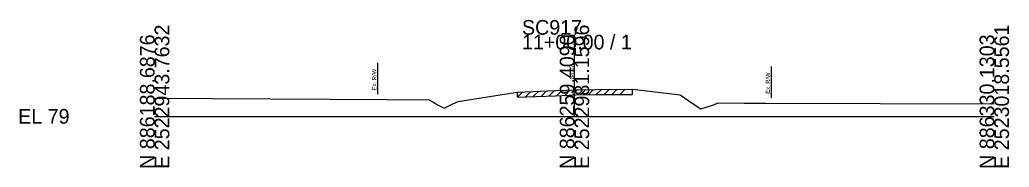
# Model space of a CAD drawing. Extents: x -26 to 218, y -10 to 12021.
# Drawn here: x -25.7 to 162.8, y 9490.3 to 9518.4 of the extents above; entities that cross this region are included whole.
import ezdxf

# ---------------------------------------------------------------- set-up
doc = ezdxf.new("R2010")
doc.units = 0
for name, color, linetype in [('RD_GPK_XS_Cell', 7, 'Continuous'), ('RD_XS_ExGround', 7, 'Continuous'), ('RD_XS_ExPaveRet', 7, 'Continuous'), ('RD_XS_ExRW', 7, 'Continuous'), ('RD_XS_TX_Elev_EX', 7, 'Continuous')]:
    doc.layers.add(name, color=color, linetype=linetype)

msp = doc.modelspace()

# ---------------------------------------------------------------- linework, layer by layer
at = {"layer": 'RD_GPK_XS_Cell'}
for p, q in [((80, 9500), (80, 9515.55)), ((0, 9500), (80, 9500)), ((80, 9500), (160, 9500))]:
    msp.add_line(p, q, dxfattribs=at)
at = {"layer": 'RD_XS_ExGround'}
for p, q in [((57.86, 9502.84), (65.01, 9504)), ((65.01, 9504), (69.14, 9504.63)), ((69.14, 9504.63), (76.39, 9504.93)), ((76.39, 9504.93), (80.26, 9505.08)), ((80.26, 9505.08), (84.01, 9505.13)), ((84.01, 9505.13), (90.97, 9505.18)), ((90.97, 9505.18), (94.28, 9504.8)), ((94.28, 9504.8), (100.16, 9504.07)), ((100.16, 9504.07), (102.62, 9502.4)), ((0, 9503.48), (44.33, 9503.19)), ((44.33, 9503.19), (52.37, 9503.12)), ((52.37, 9503.12), (54.06, 9502.15)), ((54.06, 9502.15), (55.2, 9501.56)), ((55.2, 9501.56), (56.85, 9502.36)), ((56.85, 9502.36), (57.86, 9502.84)), ((102.62, 9502.4), (104.08, 9501.42)), ((104.08, 9501.42), (106.31, 9502.16)), ((106.31, 9502.16), (107.45, 9502.58)), ((107.45, 9502.58), (112.36, 9502.54)), ((112.36, 9502.54), (116.55, 9502.52)), ((116.55, 9502.52), (160, 9502.38))]:
    msp.add_line(p, q, dxfattribs=at)
at = {"layer": 'RD_XS_ExPaveRet'}
for p, q in [((69.14, 9503.63), (70.18, 9504.67)), ((69.14, 9503.63), (69.14, 9504.63)), ((70.64, 9503.69), (71.68, 9504.73)), ((72.14, 9503.75), (73.18, 9504.79)), ((73.64, 9503.81), (74.68, 9504.86)), ((75.14, 9503.87), (76.18, 9504.92)), ((76.39, 9503.93), (80.26, 9504.08)), ((76.64, 9503.94), (77.68, 9504.98)), ((78.14, 9504), (79.18, 9505.04)), ((79.64, 9504.05), (80.67, 9505.09)), ((80.26, 9504.08), (84.01, 9504.13)), ((81.14, 9504.09), (82.15, 9505.11)), ((82.64, 9504.11), (83.65, 9505.13)), ((84.01, 9504.13), (90.97, 9504.18)), ((84.14, 9504.13), (85.15, 9505.14)), ((85.64, 9504.15), (86.65, 9505.15)), ((87.14, 9504.16), (88.15, 9505.16)), ((88.64, 9504.17), (89.65, 9505.18)), ((90.97, 9505.18), (90.97, 9504.18)), ((69.14, 9503.63), (76.39, 9503.93))]:
    msp.add_line(p, q, dxfattribs=at)
at = {"layer": 'RD_XS_ExRW'}
for p, q in [((42.5, 9510.2), (42.5, 9504.2)), ((117.5, 9509.52), (117.5, 9503.52)), ((117.5, 9509.52), (117.5, 9503.52))]:
    msp.add_line(p, q, dxfattribs=at)

# ---------------------------------------------------------------- texts
at = {"layer": 'RD_GPK_XS_Cell'}
for s, p in [('E 2522943.7632', (2.8, 9490)), ('E 2522981.1596', (82.8, 9490)), ('E 2523018.5561', (162.8, 9490)), ('N 886188.6876', (0, 9490)), ('N 886259.4090', (80, 9490)), ('N 886330.1303', (160, 9490))]:
    msp.add_text(s, height=2.8, rotation=90, dxfattribs=at).set_placement(p)
for s, p in [('SC917', (70, 9515.55)), ('11+00.00 / 1', (70, 9512.75)), ('EL 79', (-26, 9498.6))]:
    msp.add_text(s, height=2.8, dxfattribs=at).set_placement(p)
at = {"layer": 'RD_XS_ExRW'}
for p in [(42.25, 9504.99), (117.25, 9504.31), (117.25, 9504.31)]:
    msp.add_text('Ex. R/W ', height=0.8, rotation=90, dxfattribs=at).set_placement(p)
at = {"layer": 'RD_XS_TX_Elev_EX'}
msp.add_text('84.07', height=0.8, rotation=90, dxfattribs=at).set_placement((79.9, 9507.07))

doc.saveas('drawing.dxf')
